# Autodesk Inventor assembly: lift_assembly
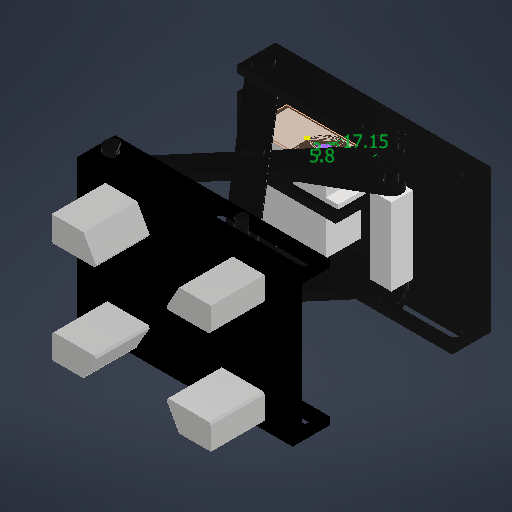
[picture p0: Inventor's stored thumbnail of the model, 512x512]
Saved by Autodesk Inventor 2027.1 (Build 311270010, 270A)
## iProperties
Created: 2026-11
Part Number: lift_assembly
Document SubType Name: Assembly
Designer: djshs
Author: djshs
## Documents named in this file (16)
- C:\Users\djshs\OneDrive\Desktop\ROKEY BOOT CAMP\project1\lift\lift_assembly.iam
- C:\Users\djshs\OneDrive\Desktop\ROKEY BOOT CAMP\project1\lift\02_상판_x1.ipt
- C:\Users\djshs\OneDrive\Desktop\ROKEY BOOT CAMP\project1\lift\01_하판_x1.ipt
- C:\Users\djshs\OneDrive\Desktop\ROKEY BOOT CAMP\project1\lift\motor_mesh.ipt
- C:\Users\djshs\OneDrive\Desktop\ROKEY BOOT CAMP\project1\lift\07_크랭크_스플라인5.9_x1.ipt
- C:\Users\djshs\OneDrive\Desktop\ROKEY BOOT CAMP\project1\lift\06_푸시로드_x1.ipt
- C:\Users\djshs\OneDrive\Desktop\ROKEY BOOT CAMP\project1\lift\03_시저팔_바깥A_x2.ipt
- C:\Users\djshs\OneDrive\Desktop\ROKEY BOOT CAMP\project1\lift\10_핀6_아래고정_x2.ipt
- C:\Users\djshs\OneDrive\Desktop\ROKEY BOOT CAMP\project1\lift\14_클립6_x8.ipt
- C:\Users\djshs\OneDrive\Desktop\ROKEY BOOT CAMP\project1\lift\03_시저팔_안쪽B_x2.ipt
- C:\Users\djshs\OneDrive\Desktop\ROKEY BOOT CAMP\project1\lift\08_슬라이더축_x2.ipt
- C:\Users\djshs\OneDrive\Desktop\ROKEY BOOT CAMP\project1\lift\09_스페이서_x6.ipt
- C:\Users\djshs\OneDrive\Desktop\ROKEY BOOT CAMP\project1\lift\11_핀6_가운데_x2.ipt
- C:\Users\djshs\OneDrive\Desktop\ROKEY BOOT CAMP\project1\lift\12_핀6_위고정_x2.ipt
- C:\Users\djshs\OneDrive\Desktop\ROKEY BOOT CAMP\project1\lift\아래슬라이더바.ipt
- C:\Users\djshs\OneDrive\Desktop\ROKEY BOOT CAMP\project1\lift\05_위슬라이더바_x1.ipt
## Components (28 placed, 14 different names)
1. 01_하판_x1:1
2. motor_mesh:1 — 플러쉬:1
3. 07_크랭크_스플라인5.9_x1:1 — 플러쉬:1
4. 06_푸시로드_x1:1
5. 03_시저팔_바깥A_x2:1
6. 10_핀6_아래고정_x2:1
7. 14_클립6_x8:1
8. 03_시저팔_안쪽B_x2:1
9. 08_슬라이더축_x2:1
10. 09_스페이서_x6:1
11. 11_핀6_가운데_x2:1
12. 02_상판_x1:1
13. 08_슬라이더축_x2:2
14. 12_핀6_위고정_x2:1
15. 09_스페이서_x6:2
16. 10_핀6_아래고정_x2:2
17. 03_시저팔_바깥A_x2:2
18. 03_시저팔_안쪽B_x2:2
19. 14_클립6_x8:2
20. 14_클립6_x8:3
21. 09_스페이서_x6:3
22. 09_스페이서_x6:4
23. 12_핀6_위고정_x2:2
24. 14_클립6_x8:4
25. 05_위슬라이더바_x1:1 — 각도:2
26. 09_스페이서_x6:5
27. 09_스페이서_x6:6
28. 11_핀6_가운데_x2:2
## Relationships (2: Flush 1, Angle 1)
- 플러쉬:1 [Flush]: motor_mesh:1 ↔ 07_크랭크_스플라인5.9_x1:1
- 각도:2 [Angle]: 05_위슬라이더바_x1:1
